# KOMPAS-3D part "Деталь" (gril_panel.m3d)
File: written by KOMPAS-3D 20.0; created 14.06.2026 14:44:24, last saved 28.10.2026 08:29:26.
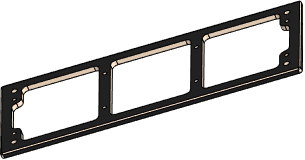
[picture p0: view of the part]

Document properties: Полное имя файла: D:\RicWork\Project-EPS32\box_compas\корпус\gril_panel.m3d

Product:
- Part/product: Деталь
    Масса: 0.184328
  - Body: Тело 1
      Масса: 0.18542

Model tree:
1. Эскиз:1
2. Элемент выдавливания:1
     Расстояние 1 = 4
3. Эскиз:7  (with: Элемент выдавливания:1)
4. Эскиз:8  (with: Элемент выдавливания:1)
5. Элемент выдавливания:9
     Расстояние 2 = 4
6. Элемент выдавливания:12
     Расстояние 2 = 4
7. Элемент выдавливания:13
     Расстояние 2 = 4
8. Элемент выдавливания:14
     Расстояние 2 = 4
9. Элемент выдавливания:15  (with: Элемент выдавливания:14, Элемент выдавливания:13, Элемент выдавливания:12)
     Расстояние 1 = 3
10. Элемент выдавливания:16  (with: Элемент выдавливания:14, Элемент выдавливания:13, Элемент выдавливания:12)
     Расстояние 1 = 3
11. Скругление:4  (with: Элемент выдавливания:15, Элемент выдавливания:14, Элемент выдавливания:16, Элемент выдавливания:12)
     Радиус = 4
12. Скругление:5  (with: Элемент выдавливания:1)
     Радиус = 1
13. Скругление:6  (with: Элемент выдавливания:1)
     Радиус = 2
